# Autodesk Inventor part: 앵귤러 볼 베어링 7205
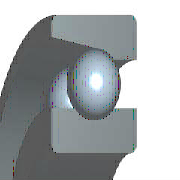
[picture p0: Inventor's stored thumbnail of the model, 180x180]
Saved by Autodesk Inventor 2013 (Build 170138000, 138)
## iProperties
Created: 2012-02
Part Number: 앵귤러 볼 베어링 7205
Material: 강철, 연강
Description: 앵귤러 콘택트 볼 베어링
Document SubType Name: Modeling
Standard: KS B 2024
Designer: mduedu
Standards Organization: KS
Language: ko-KR
Size Designation: 7205 - 25 x 52 x 15
Categories: <MemberInstance><Categories><Category DisplayName="샤프트 부품" InternalName="7f7aeb1f-a693-4053-b835-cee3144e0d98" Mnemonic="SHFT"><Category DisplayName="베어링" Inter
Density: 1 g/cm^3
IsCustomPart: 1
Author: mduedu
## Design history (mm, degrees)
sketch "스케치" dims "d1" = 7.02 (= -0.26 x WD + 0.26 x BD)
  geometry: L1 (3.99, 19.25)-(11.01, 19.25); L2 (7.5, 22.76)-(7.5, 15.74); L3 (0, 16.901)-(4.892, 16.901); L4 (0, 12.5)-(15, 12.5); L5 (8.11, 22.707)-(0, 24.137); L6 (15, 16.901)-(15, 12.5); L7 (15, 16.901)-(10.108, 16.901); L8 (15, 21.599)-(10.108, 21.599); L9 (15, 21.599)-(15, 26); L10 (0, 26)-(15, 26); L11 (-2.4, 0)-(14.4, 0) reference; L12 (0, -1.44)-(0, 8.99) reference; 1 further point
  constraints: 20 end point, 4 point on line, 3 symmetric about line, 2 midpoint, 2 parallel, 1 perpendicular, 14 other
  dimensions: "d0" = 10 deg angle of L8 L5; "d11" = 25 diameter of L4 L11 (= WD); "d12" = 52 diameter of L10 L11 (= BD); "d13" = 15 distance between parallel lines of L6 L12 (= KB); "d14" = 33.802 diameter of L7 L11 (= 0.326 x BD + 0.674 x WD)
revolve "본체" stored, may be unused: angle "d6" = 90 deg
revolve "볼" stored, may be unused: angle "d8" = 90 deg
pattern_circular "IDS_ARRAYBALL[SIMPL:T]" dims angle "d4" = 360 deg
body "Solid1"
fillet "모깎기1" dims "d2" = 1 (= KRS)
other parameters: "WD" = 25 [user parameter; used in 5 equation terms], "BD" = 52 [user parameter; used in 5 equation terms], "KB" = 15 [user parameter; used in 1 equation term], "KRS" = 1 [user parameter; used in 1 equation term], "d5" = 0, "d7" = 0, "d9" = 0, "d15" = 0, "d16" = 0, "BC0" = 1.02e+07 [user parameter], "BBA" = 30 deg [user parameter], "BC" = 1.56e+07 [user parameter], "KR1S" = 0.6 [user parameter], "BR" = 26 (= 0.5 x BD) [user parameter], "WR" = 12.5 (= 0.5 x WD) [user parameter]
